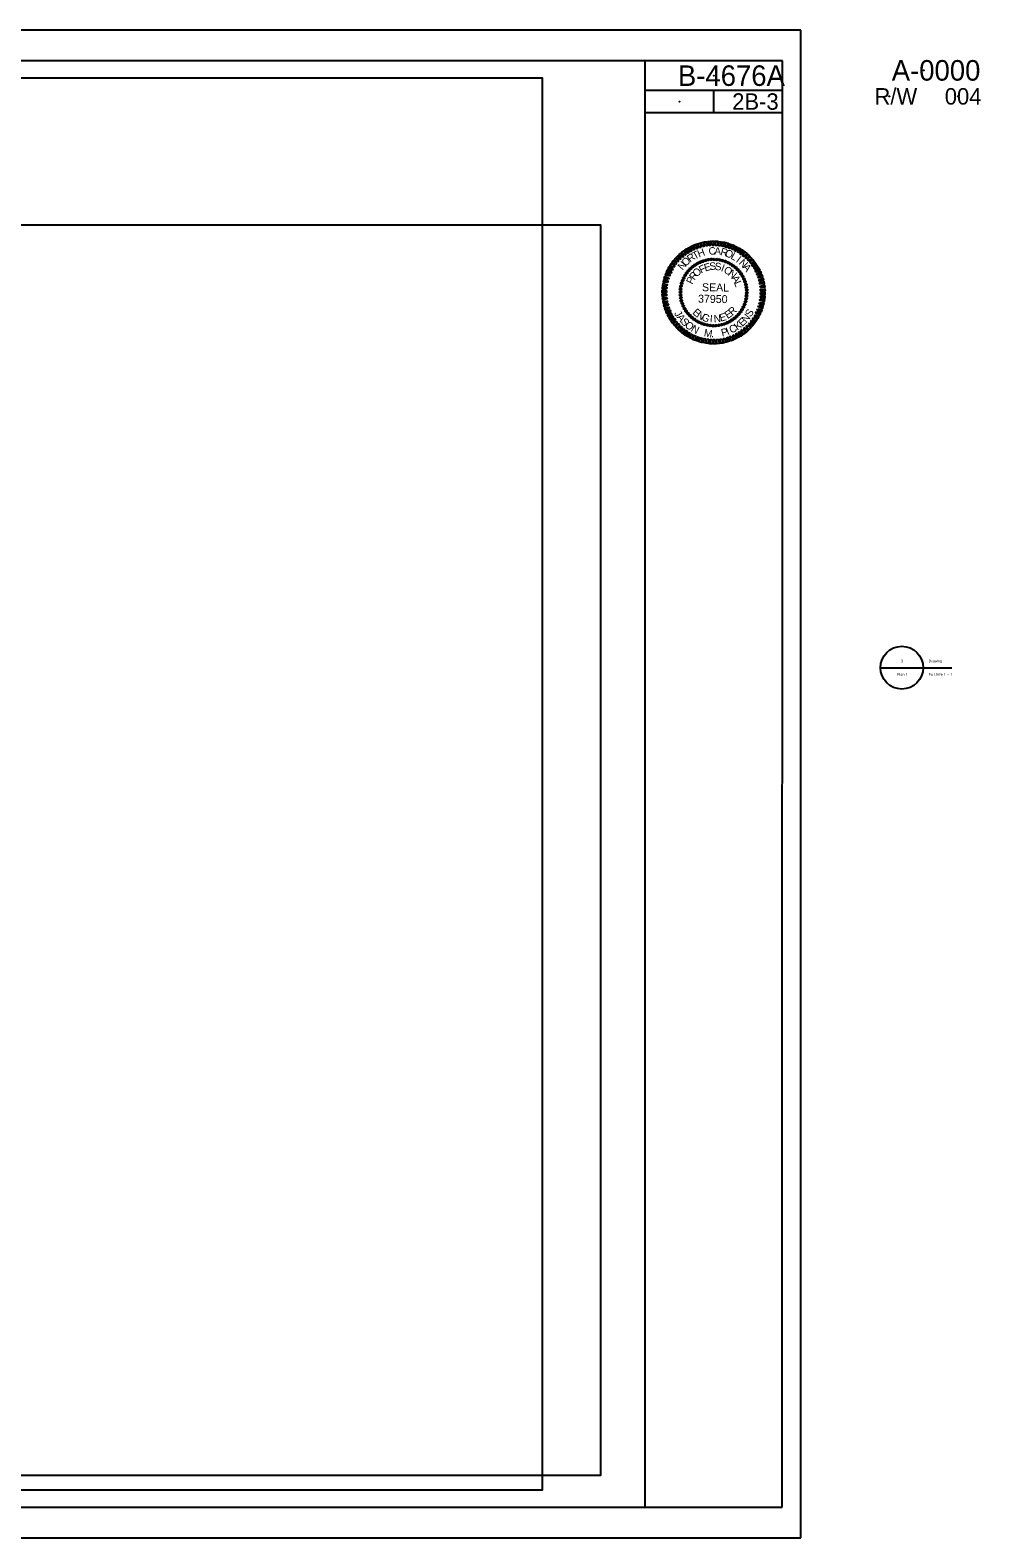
# Model space of a CAD drawing. Extents: x 0 to 3.05, y -0.01 to 1.83.
# Drawn here: x 1.896 to 3.052, y 0 to 1.833 of the extents above; entities that cross this region are included whole.
import ezdxf

# ---------------------------------------------------------------- set-up
doc = ezdxf.new("R2010")
doc.units = 0
for name, color, linetype in [('HNTB LOGO CELL', 7, 'Continuous'), ('Matchline Text', 7, 'Continuous'), ('Prop North Arrow for Plan Sheets CELL', 7, 'Continuous'), ('Sheet Clip Boundary CELL', 7, 'Continuous'), ('Sheet Data Field CELL', 7, 'Continuous'), ('Sheet Plan And Profile CELL', 7, 'Continuous')]:
    doc.layers.add(name, color=color, linetype=linetype)

msp = doc.modelspace()

# ---------------------------------------------------------------- linework, layer by layer
at = {"layer": 'HNTB LOGO CELL'}
for p, q in [((2.93, 1.0581), (2.9821, 1.0581)), ((2.9563, 1.0581), (3.017, 1.0581))]:
    msp.add_line(p, q, dxfattribs=at)
msp.add_circle((2.9561, 1.0581), 0.026, dxfattribs=at)
at = {"layer": 'Matchline Text'}
for centre in [(2.9826, 1.7844), (2.9409, 1.7528), (3.0243, 1.7528)]:
    msp.add_circle(centre, 0.0001, dxfattribs=at)
at = {"layer": 'Prop North Arrow for Plan Sheets CELL'}
for p, q in [((2.6967, 1.5408), (2.6967, 1.5408)), ((2.6991, 1.5433), (2.6991, 1.5433)), ((2.7018, 1.5457), (2.7018, 1.5457)), ((2.7046, 1.5478), (2.7046, 1.5478)), ((2.7076, 1.5496), (2.7076, 1.5496)), ((2.7108, 1.5512), (2.7108, 1.5512)), ((2.714, 1.5525), (2.714, 1.5525)), ((2.7174, 1.5535), (2.7174, 1.5535)), ((2.7209, 1.5541), (2.7209, 1.5541)), ((2.7244, 1.5546), (2.7244, 1.5546)), ((2.7279, 1.5547), (2.7279, 1.5547)), ((2.7315, 1.5544), (2.7315, 1.5544)), ((2.7349, 1.5539), (2.7349, 1.5539)), ((2.7383, 1.5532), (2.7383, 1.5532)), ((2.7417, 1.552), (2.7417, 1.552)), ((2.7449, 1.5506), (2.7449, 1.5506)), ((2.748, 1.549), (2.748, 1.549)), ((2.7509, 1.547), (2.7509, 1.547)), ((2.7538, 1.5448), (2.7538, 1.5448)), ((2.7563, 1.5424), (2.7563, 1.5424)), ((2.6876, 1.522), (2.6876, 1.522)), ((2.6883, 1.5254), (2.6883, 1.5254)), ((2.6895, 1.5288), (2.6895, 1.5288)), ((2.6909, 1.532), (2.6909, 1.532)), ((2.6925, 1.5351), (2.6925, 1.5351)), ((2.6945, 1.538), (2.6945, 1.538)), ((2.7587, 1.5397), (2.7587, 1.5397)), ((2.7607, 1.5369), (2.7607, 1.5369)), ((2.7625, 1.5338), (2.7625, 1.5338)), ((2.7641, 1.5307), (2.7641, 1.5307)), ((2.7654, 1.5275), (2.7654, 1.5275)), ((2.7664, 1.5241), (2.7664, 1.5241)), ((2.6868, 1.515), (2.6868, 1.515)), ((2.6869, 1.5115), (2.6869, 1.5115)), ((2.687, 1.5185), (2.687, 1.5185)), ((2.6874, 1.508), (2.6874, 1.508)), ((2.688, 1.5045), (2.688, 1.5045)), ((2.7272, 1.5143), (2.7272, 1.5143)), ((2.7668, 1.5066), (2.7668, 1.5066)), ((2.767, 1.5206), (2.767, 1.5206)), ((2.7674, 1.51), (2.7674, 1.51)), ((2.7675, 1.5171), (2.7675, 1.5171)), ((2.7676, 1.5136), (2.7676, 1.5136)), ((2.689, 1.5011), (2.689, 1.5011)), ((2.6903, 1.4979), (2.6903, 1.4979)), ((2.6919, 1.4947), (2.6919, 1.4947)), ((2.6937, 1.4917), (2.6937, 1.4917)), ((2.6957, 1.4888), (2.6957, 1.4888)), ((2.6981, 1.4862), (2.6981, 1.4862)), ((2.7553, 1.4852), (2.7553, 1.4852)), ((2.7577, 1.4877), (2.7577, 1.4877)), ((2.7599, 1.4905), (2.7599, 1.4905)), ((2.7619, 1.4934), (2.7619, 1.4934)), ((2.7635, 1.4966), (2.7635, 1.4966)), ((2.7649, 1.4998), (2.7649, 1.4998)), ((2.7661, 1.5032), (2.7661, 1.5032)), ((2.7006, 1.4838), (2.7006, 1.4838)), ((2.7035, 1.4816), (2.7035, 1.4816)), ((2.7064, 1.4796), (2.7064, 1.4796)), ((2.7095, 1.478), (2.7095, 1.478)), ((2.7127, 1.4765), (2.7127, 1.4765)), ((2.7161, 1.4754), (2.7161, 1.4754)), ((2.7195, 1.4747), (2.7195, 1.4747)), ((2.7229, 1.4741), (2.7229, 1.4741)), ((2.7265, 1.4739), (2.7265, 1.4739)), ((2.73, 1.474), (2.73, 1.474)), ((2.7335, 1.4744), (2.7335, 1.4744)), ((2.737, 1.4751), (2.737, 1.4751)), ((2.7404, 1.476), (2.7404, 1.476)), ((2.7436, 1.4773), (2.7436, 1.4773)), ((2.7468, 1.4789), (2.7468, 1.4789)), ((2.7498, 1.4808), (2.7498, 1.4808)), ((2.7526, 1.4828), (2.7526, 1.4828))]:
    msp.add_line(p, q, dxfattribs=at)
for points in [[(2.7253, 1.5715), (2.7249, 1.5767), (2.7275, 1.5766), (2.7272, 1.5714)], [(2.7291, 1.5714), (2.7291, 1.5766), (2.7318, 1.5766), (2.7311, 1.5713)], [(2.6862, 1.554), (2.6821, 1.5573), (2.6841, 1.5592), (2.6875, 1.5553)], [(2.6889, 1.5569), (2.6854, 1.5604), (2.6873, 1.5623), (2.6904, 1.558)], [(2.6921, 1.5593), (2.6887, 1.5632), (2.6908, 1.5649), (2.6936, 1.5604)], [(2.6952, 1.5618), (2.6922, 1.5659), (2.6943, 1.5674), (2.6969, 1.5627)], [(2.6987, 1.5638), (2.6957, 1.5681), (2.6982, 1.5694), (2.7002, 1.5647)], [(2.7022, 1.5657), (2.6996, 1.5702), (2.7021, 1.5713), (2.7039, 1.5664)], [(2.7057, 1.5674), (2.7036, 1.5721), (2.706, 1.573), (2.7077, 1.5679)], [(2.7097, 1.5687), (2.7078, 1.5735), (2.7103, 1.5742), (2.7113, 1.5692)], [(2.7135, 1.5697), (2.7118, 1.5748), (2.7146, 1.5754), (2.7152, 1.5701)], [(2.7174, 1.5706), (2.7161, 1.5758), (2.7187, 1.576), (2.7193, 1.5709)], [(2.7212, 1.5711), (2.7204, 1.5763), (2.7231, 1.5766), (2.7232, 1.5713)], [(2.7332, 1.5712), (2.7335, 1.5764), (2.7361, 1.5759), (2.7351, 1.5709)], [(2.737, 1.5705), (2.7377, 1.5757), (2.7404, 1.5753), (2.739, 1.5703)], [(2.7411, 1.5696), (2.7419, 1.5749), (2.7447, 1.5742), (2.7428, 1.5692)], [(2.745, 1.5686), (2.7462, 1.5736), (2.7487, 1.5728), (2.7467, 1.568)], [(2.7486, 1.5672), (2.7505, 1.5722), (2.7527, 1.5713), (2.7505, 1.5666)], [(2.7522, 1.5656), (2.7542, 1.5704), (2.7567, 1.5692), (2.754, 1.5647)], [(2.7559, 1.5638), (2.7581, 1.5684), (2.7605, 1.567), (2.7575, 1.5628)], [(2.7591, 1.5616), (2.7619, 1.5663), (2.764, 1.5646), (2.7608, 1.5606)], [(2.7624, 1.5592), (2.7653, 1.5636), (2.7674, 1.5618), (2.7639, 1.5581)], [(2.7654, 1.5567), (2.7687, 1.5609), (2.7707, 1.5589), (2.767, 1.5555)], [(2.6751, 1.5375), (2.6701, 1.5394), (2.6713, 1.5419), (2.6759, 1.5393)], [(2.6767, 1.5412), (2.6721, 1.5433), (2.6733, 1.5457), (2.6776, 1.5428)], [(2.6786, 1.5447), (2.6741, 1.5471), (2.6757, 1.5494), (2.6799, 1.5462)], [(2.681, 1.5479), (2.6767, 1.5507), (2.6782, 1.553), (2.6821, 1.5494)], [(2.6834, 1.551), (2.6792, 1.5541), (2.681, 1.5562), (2.6845, 1.5524)], [(2.7683, 1.5539), (2.7718, 1.5577), (2.7737, 1.5557), (2.7695, 1.5526)], [(2.7711, 1.551), (2.7748, 1.5546), (2.7765, 1.5524), (2.7723, 1.5494)], [(2.7736, 1.5478), (2.7775, 1.5512), (2.779, 1.5489), (2.7745, 1.5463)], [(2.7756, 1.5445), (2.7799, 1.5476), (2.7814, 1.5452), (2.7768, 1.5429)], [(2.7777, 1.541), (2.7822, 1.5438), (2.7833, 1.5413), (2.7787, 1.5395)], [(2.6705, 1.5222), (2.6654, 1.5226), (2.6657, 1.5254), (2.6709, 1.5241)], [(2.6712, 1.5263), (2.6662, 1.5269), (2.6668, 1.5296), (2.6718, 1.528)], [(2.6722, 1.5301), (2.6672, 1.5312), (2.6678, 1.5338), (2.6729, 1.5318)], [(2.6734, 1.534), (2.6685, 1.5354), (2.6695, 1.5379), (2.6743, 1.5357)], [(2.7794, 1.5375), (2.7841, 1.54), (2.7851, 1.5374), (2.7802, 1.5358)], [(2.7808, 1.5338), (2.7857, 1.5358), (2.7866, 1.5334), (2.7816, 1.5321)], [(2.7821, 1.5299), (2.7872, 1.5317), (2.7877, 1.5291), (2.7827, 1.5282)], [(2.7831, 1.526), (2.7881, 1.5276), (2.7886, 1.5248), (2.7835, 1.5243)], [(2.7838, 1.5222), (2.789, 1.5233), (2.7893, 1.5206), (2.7841, 1.5202)], [(2.6701, 1.5143), (2.6648, 1.514), (2.6648, 1.5168), (2.6701, 1.5162)], [(2.6701, 1.5103), (2.6649, 1.5096), (2.6648, 1.5123), (2.67, 1.5122)], [(2.6701, 1.5183), (2.6649, 1.5185), (2.6651, 1.5211), (2.6703, 1.5202)], [(2.6706, 1.5064), (2.6654, 1.5053), (2.6652, 1.508), (2.6703, 1.5083)], [(2.6713, 1.5025), (2.6663, 1.501), (2.6658, 1.5037), (2.6709, 1.5042)], [(2.7839, 1.5064), (2.789, 1.5059), (2.7887, 1.5032), (2.7835, 1.5045)], [(2.7843, 1.5103), (2.7895, 1.5101), (2.7893, 1.5074), (2.7841, 1.5083)], [(2.7843, 1.5183), (2.7895, 1.5189), (2.7897, 1.5162), (2.7844, 1.5164)], [(2.7843, 1.5143), (2.7896, 1.5145), (2.7896, 1.5118), (2.7843, 1.5123)], [(2.6723, 1.4987), (2.6672, 1.4968), (2.6667, 1.4995), (2.6717, 1.5004)], [(2.6736, 1.4948), (2.6687, 1.4927), (2.6678, 1.4952), (2.6728, 1.4965)], [(2.6751, 1.491), (2.6703, 1.4886), (2.6693, 1.4912), (2.6742, 1.4928)], [(2.6767, 1.4876), (2.6722, 1.4847), (2.6711, 1.4872), (2.6757, 1.4891)], [(2.6788, 1.484), (2.6745, 1.481), (2.673, 1.4834), (2.6776, 1.4856)], [(2.7777, 1.4873), (2.7823, 1.4853), (2.7811, 1.4828), (2.7768, 1.4858)], [(2.7794, 1.491), (2.7843, 1.4892), (2.7831, 1.4867), (2.7785, 1.4893)], [(2.781, 1.4946), (2.786, 1.4931), (2.7849, 1.4906), (2.7801, 1.4929)], [(2.7822, 1.4984), (2.7872, 1.4974), (2.7866, 1.4947), (2.7815, 1.4967)], [(2.7832, 1.5023), (2.7882, 1.5016), (2.7876, 1.4989), (2.7826, 1.5006)], [(2.6808, 1.4807), (2.6769, 1.4773), (2.6754, 1.4797), (2.6799, 1.4823)], [(2.6833, 1.4776), (2.6796, 1.474), (2.6779, 1.4761), (2.6821, 1.4792)], [(2.6861, 1.4747), (2.6826, 1.4709), (2.6807, 1.4728), (2.6849, 1.476)], [(2.689, 1.4719), (2.6857, 1.4677), (2.6837, 1.4696), (2.6874, 1.4731)], [(2.692, 1.4694), (2.6891, 1.4649), (2.687, 1.4667), (2.6905, 1.4705)], [(2.6953, 1.467), (2.6925, 1.4623), (2.6904, 1.464), (2.6936, 1.4679)], [(2.7592, 1.4668), (2.7622, 1.4627), (2.7601, 1.4612), (2.7575, 1.4658)], [(2.7623, 1.4692), (2.7658, 1.4653), (2.7636, 1.4637), (2.7608, 1.4682)], [(2.7655, 1.4717), (2.7691, 1.4682), (2.7671, 1.4662), (2.764, 1.4706)], [(2.7682, 1.4745), (2.7723, 1.4712), (2.7703, 1.4694), (2.7669, 1.4732)], [(2.771, 1.4776), (2.7752, 1.4744), (2.7734, 1.4724), (2.7699, 1.4761)], [(2.7734, 1.4806), (2.7777, 1.4779), (2.7762, 1.4756), (2.7723, 1.4791)], [(2.7758, 1.4839), (2.7803, 1.4814), (2.7787, 1.4792), (2.7745, 1.4824)], [(2.6985, 1.4648), (2.6963, 1.4602), (2.6939, 1.4616), (2.6969, 1.4657)], [(2.7022, 1.4629), (2.7002, 1.4582), (2.6977, 1.4593), (2.7004, 1.4638)], [(2.7058, 1.4614), (2.7039, 1.4563), (2.7017, 1.4573), (2.7039, 1.462)], [(2.7094, 1.46), (2.7082, 1.455), (2.7057, 1.4558), (2.7077, 1.4605)], [(2.7133, 1.4589), (2.7125, 1.4537), (2.7097, 1.4543), (2.7116, 1.4593)], [(2.7174, 1.458), (2.7167, 1.4529), (2.714, 1.4533), (2.7155, 1.4583)], [(2.7212, 1.4574), (2.7209, 1.4522), (2.7183, 1.4526), (2.7193, 1.4577)], [(2.7253, 1.4571), (2.7253, 1.4519), (2.7226, 1.452), (2.7233, 1.4572)], [(2.7291, 1.4571), (2.7295, 1.4518), (2.7269, 1.4519), (2.7272, 1.4571)], [(2.7332, 1.4575), (2.734, 1.4523), (2.7313, 1.452), (2.7312, 1.4572)], [(2.737, 1.4579), (2.7383, 1.4528), (2.7357, 1.4526), (2.7351, 1.4577)], [(2.7409, 1.4588), (2.7426, 1.4538), (2.7398, 1.4532), (2.7392, 1.4584)], [(2.7447, 1.4599), (2.7466, 1.455), (2.7441, 1.4543), (2.7431, 1.4593)], [(2.7487, 1.4612), (2.7508, 1.4565), (2.7484, 1.4555), (2.7467, 1.4607)], [(2.7522, 1.4629), (2.7548, 1.4583), (2.7523, 1.4572), (2.7505, 1.4621)], [(2.7557, 1.4648), (2.7587, 1.4604), (2.7562, 1.4592), (2.7542, 1.4638)]]:
    msp.add_lwpolyline(points, close=True, dxfattribs=at)
for centre, major_axis, ratio in [((2.6967, 1.5408), (-0.000878, 0.000757), 0.999708), ((2.6992, 1.5433), (-0.000809, 0.00083), 0.999708), ((2.7018, 1.5457), (-0.000733, 0.000898), 0.999709), ((2.7046, 1.5477), (-0.000652, 0.000958), 0.999709), ((2.7076, 1.5496), (-0.00057, 0.00101), 0.99971), ((2.7108, 1.5512), (-0.00047, 0.00106), 0.99971), ((2.7141, 1.5524), (-0.00038, 0.00109), 0.99971), ((2.7174, 1.5534), (-0.00028, 0.00112), 0.99971), ((2.7209, 1.5542), (-0.00018, 0.00114), 0.999711), ((2.7244, 1.5546), (-0.00008, 0.00116), 0.999711), ((2.7279, 1.5546), (0.00002, 0.00116), 0.999711), ((2.7314, 1.5544), (0.00012, 0.00115), 0.999711), ((2.7349, 1.5539), (0.00022, 0.00114), 0.999711), ((2.7383, 1.5531), (0.00032, 0.00111), 0.99971), ((2.7417, 1.552), (0.00042, 0.00108), 0.99971), ((2.7449, 1.5506), (0.00051, 0.00104), 0.99971), ((2.748, 1.5489), (0.0006, 0.000991), 0.99971), ((2.7509, 1.5469), (0.000685, 0.000935), 0.999709), ((2.7537, 1.5447), (0.000764, 0.000871), 0.999709), ((2.7562, 1.5423), (0.000837, 0.000802), 0.999708), ((2.7586, 1.5397), (0.000904, 0.000726), 0.999708), ((2.6876, 1.522), (-0.00114, 0.00022), 0.999706), ((2.6884, 1.5254), (-0.00111, 0.00032), 0.999706), ((2.6895, 1.5287), (-0.00108, 0.00041), 0.999706), ((2.6909, 1.532), (-0.00104, 0.0005), 0.999707), ((2.6926, 1.5351), (-0.000996, 0.000593), 0.999707), ((2.6945, 1.538), (-0.00094, 0.000678), 0.999707), ((2.7607, 1.5369), (0.000963, 0.000644), 0.999707), ((2.7625, 1.5339), (0.00102, 0.00056), 0.999707), ((2.7641, 1.5307), (0.00106, 0.00047), 0.999707), ((2.7654, 1.5274), (0.0011, 0.00037), 0.999706), ((2.7664, 1.524), (0.00113, 0.00028), 0.999706), ((2.7671, 1.5206), (0.00114, 0.00018), 0.999706), ((2.6868, 1.515), (-0.00116, 0.00002), 0.999706), ((2.6869, 1.5115), (-0.00116, -0.00008), 0.999706), ((2.687, 1.5185), (-0.00115, 0.00012), 0.999706), ((2.6873, 1.508), (-0.00114, -0.00018), 0.999706), ((2.688, 1.5045), (-0.00113, -0.00028), 0.999706), ((2.766, 1.5032), (0.00111, -0.00032), 0.999706), ((2.7668, 1.5066), (0.00114, -0.00022), 0.999706), ((2.7673, 1.5101), (0.00115, -0.00012), 0.999706), ((2.7675, 1.5171), (0.00116, 0.00008), 0.999706), ((2.7676, 1.5136), (0.00116, -0.00002), 0.999706), ((2.689, 1.5011), (-0.0011, -0.00037), 0.999706), ((2.6903, 1.4979), (-0.00106, -0.00047), 0.999707), ((2.6919, 1.4947), (-0.00102, -0.00056), 0.999707), ((2.6937, 1.4917), (-0.000963, -0.000644), 0.999707), ((2.6958, 1.4889), (-0.000904, -0.000726), 0.999708), ((2.6982, 1.4862), (-0.000837, -0.000802), 0.999708), ((2.7007, 1.4838), (-0.000764, -0.000871), 0.999709), ((2.7552, 1.4852), (0.000809, -0.00083), 0.999708), ((2.7577, 1.4878), (0.000878, -0.000757), 0.999708), ((2.7599, 1.4906), (0.00094, -0.000678), 0.999707), ((2.7618, 1.4935), (0.000996, -0.000593), 0.999707), ((2.7635, 1.4966), (0.00104, -0.0005), 0.999707), ((2.7649, 1.4998), (0.00108, -0.00041), 0.999706), ((2.7035, 1.4816), (-0.000685, -0.000935), 0.999709), ((2.7064, 1.4797), (-0.0006, -0.000991), 0.99971), ((2.7095, 1.478), (-0.00051, -0.00104), 0.99971), ((2.7127, 1.4766), (-0.00042, -0.00108), 0.99971), ((2.7161, 1.4755), (-0.00032, -0.00111), 0.99971), ((2.7195, 1.4747), (-0.00022, -0.00114), 0.999711), ((2.723, 1.4741), (-0.00012, -0.00115), 0.999711), ((2.7265, 1.4739), (-0.00002, -0.00116), 0.999711), ((2.73, 1.474), (0.00008, -0.00116), 0.999711), ((2.7335, 1.4744), (0.00018, -0.00114), 0.999711), ((2.737, 1.4751), (0.00028, -0.00112), 0.99971), ((2.7403, 1.4761), (0.00038, -0.00109), 0.99971), ((2.7436, 1.4774), (0.00047, -0.00106), 0.99971), ((2.7468, 1.479), (0.00057, -0.00101), 0.99971), ((2.7498, 1.4808), (0.000652, -0.000958), 0.999709), ((2.7526, 1.4829), (0.000733, -0.000898), 0.999709)]:
    msp.add_ellipse(centre, major_axis=major_axis, ratio=ratio, dxfattribs=at)
at = {"layer": 'Sheet Clip Boundary CELL'}
for p, q in [((2.8108, 1.7958), (0.0608, 1.7958)), ((2.6441, 0.0375), (2.6441, 1.7958)), ((2.8107, 0.0375), (2.8108, 1.7958)), ((2.8108, 1.7601), (2.6441, 1.7601)), ((2.7275, 1.7326), (2.7275, 1.7601)), ((2.8108, 1.7326), (2.6441, 1.7326)), ((0.0607, 0.0375), (2.8107, 0.0375))]:
    msp.add_line(p, q, dxfattribs=at)
msp.add_circle((2.6441, 1.7326), 0.0001, dxfattribs=at)
at = {"layer": 'Sheet Data Field CELL'}
for p, q in [((2.8333, 1.8333), (0, 1.8333)), ((2.8333, 0), (2.8333, 1.8333)), ((0, 0), (2.8333, 0))]:
    msp.add_line(p, q, dxfattribs=at)
msp.add_lwpolyline([(0.1858, 0.0583), (2.5191, 0.0583), (2.5191, 1.775), (0.1858, 1.775)], close=True, dxfattribs=at)
for centre in [(2.7275, 1.778), (2.6858, 1.7463), (2.7691, 1.7463)]:
    msp.add_circle(centre, 0.0001, dxfattribs=at)
at = {"layer": 'Sheet Plan And Profile CELL'}
msp.add_lwpolyline([(1.381, 1.5966), (2.5898, 1.5966), (2.5898, 0.0758), (1.381, 0.0758)], close=True, dxfattribs=at)

# ---------------------------------------------------------------- texts
at = {"layer": 'HNTB LOGO CELL'}
for s, height, p in [('3', 0.00328, (2.9549, 1.0646)), ('Drawing', 0.00328, (2.9886, 1.0646)), ('Plan 1', 0.00328, (2.9502, 1.0482)), ('Full Size 1 = 1', 0.003281, (2.9886, 1.0482))]:
    msp.add_text(s, height=height, dxfattribs=at).set_placement(p)
at = {"layer": 'Matchline Text'}
for s, height, p in [('A-0000', 0.025, (2.9438, 1.7719)), ('B-4676A', 0.025, (2.6838, 1.7655)), ('R/W', 0.02, (2.9228, 1.7428)), ('004', 0.02, (3.0083, 1.7428)), ('2B-3', 0.02, (2.7498, 1.7365))]:
    msp.add_text(s, height=height, dxfattribs=at).set_placement(p)
at = {"layer": 'Prop North Arrow for Plan Sheets CELL'}
for s, height, rotation, p in [('R', 0.00908, 35.0207, (2.6987, 1.5505)), ('T', 0.00908, 27.82, (2.7042, 1.554)), ('H', 0.00908, 20.6197, (2.7094, 1.5567)), ('C', 0.00907, 6.2202, (2.7216, 1.5599)), ('A', 0.00907, 359.0206, (2.728, 1.5604)), ('R', 0.00908, 344.6214, (2.7348, 1.5601)), ('O', 0.00907, 337.4215, (2.7401, 1.5589)), ('L', 0.00908, 330.2212, (2.7472, 1.5559)), ('I', 0.00908, 323.0205, (2.7537, 1.552)), ('N', 0.00908, 49.4237, (2.6894, 1.5408)), ('O', 0.00908, 42.222, (2.6931, 1.5455)), ('O', 0.00908, 44.6815, (2.7067, 1.5325)), ('F', 0.00907, 25.9673, (2.712, 1.5373)), ('E', 0.00908, 16.6113, (2.7171, 1.5397)), ('S', 0.00907, 7.2559, (2.7227, 1.5414)), ('S', 0.00907, 357.9007, (2.7285, 1.5415)), ('I', 0.00908, 339.1899, (2.7354, 1.5404)), ('O', 0.00908, 329.8338, (2.7386, 1.5392)), ('N', 0.00908, 320.477, (2.744, 1.536)), ('N', 0.00908, 315.8193, (2.7572, 1.5495)), ('A', 0.00908, 308.6175, (2.762, 1.5448)), ('P', 0.00908, 63.3991, (2.7013, 1.5235)), ('R', 0.00908, 54.0399, (2.7039, 1.5286)), ('SEAL', 0.00965, 359.1683, (2.713, 1.5159)), ('A', 0.00908, 301.7606, (2.7486, 1.5318)), ('L', 0.00908, 292.4012, (2.7517, 1.5263)), ('37950', 0.00966, 359.0003, (2.7082, 1.502)), ('J', 0.00909, 300.574, (2.6788, 1.489)), ('A', 0.00909, 306.5844, (2.6818, 1.4841)), ('E', 0.00908, 318.2773, (2.7008, 1.4891)), ('N', 0.00908, 327.6343, (2.7056, 1.4847)), ('G', 0.00908, 336.9906, (2.7117, 1.4811)), ('I', 0.00907, 355.7015, (2.7223, 1.4781)), ('N', 0.00907, 5.0567, (2.7277, 1.4778)), ('E', 0.00908, 14.412, (2.7356, 1.4788)), ('E', 0.00908, 33.1243, (2.7442, 1.4819)), ('R', 0.00908, 42.4816, (2.7499, 1.4857)), ('N', 0.00909, 49.7832, (2.767, 1.4769)), ('S', 0.00909, 59.0604, (2.7725, 1.4838)), ('S', 0.00909, 314.7352, (2.6865, 1.478)), ('O', 0.00909, 321.981, (2.6914, 1.4731)), ('N', 0.00909, 331.7569, (2.6989, 1.4676)), ('M', 0.00909, 349.9973, (2.7149, 1.4611)), ('P', 0.00909, 13.9971, (2.7376, 1.4607)), ('I', 0.00909, 21.1137, (2.7442, 1.4624)), ('C', 0.00909, 26.2543, (2.7487, 1.4642)), ('K', 0.00909, 34.8483, (2.756, 1.4679)), ('E', 0.00909, 42.6666, (2.762, 1.4723)), ('.', 0.00909, 359.7547, (2.7241, 1.4598))]:
    msp.add_text(s, height=height, rotation=rotation, dxfattribs=at).set_placement(p)

doc.saveas('drawing.dxf')
